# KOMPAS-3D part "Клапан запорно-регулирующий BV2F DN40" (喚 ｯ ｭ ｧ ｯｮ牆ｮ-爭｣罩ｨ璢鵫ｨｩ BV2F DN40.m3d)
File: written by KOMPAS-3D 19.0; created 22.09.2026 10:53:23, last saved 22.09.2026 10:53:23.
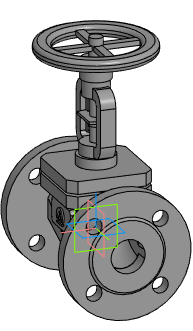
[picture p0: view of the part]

Document properties: Автор: Энергия; Полное имя файла: Z:\3.Личные\sachek\Dendor\_3D для проектировщиков\5.7 Клапан запорно-регулирующий BV2F\BV2F_STP\Клапан запорно-регулирующий BV2F DN40.m3d

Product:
- Part/product: Клапан запорно-регулирующий BV2F DN40

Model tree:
1. Операция без истории:1  (labels: Клапан запорно-регулирующий BV2F DN40)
